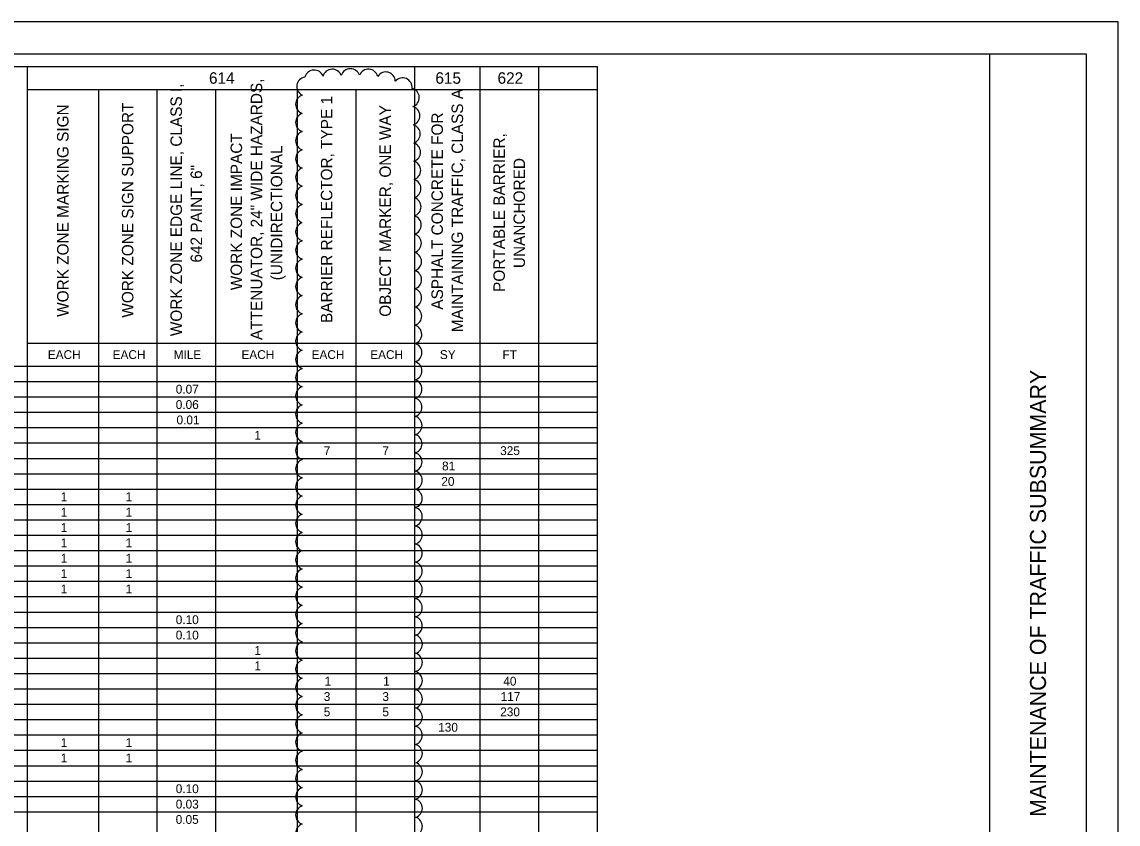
# Model space of a CAD drawing. Extents: x 0 to 36.6, y 0 to 22.
# Drawn here: x 16.89 to 34, y 9.47 to 22 of the extents above; entities that cross this region are included whole.
import ezdxf

# ---------------------------------------------------------------- set-up
doc = ezdxf.new("R2010")
doc.units = 0
for name, color, linetype in [('SC_Scratch2', 7, 'Continuous'), ('SH_Border', 7, 'Continuous'), ('SH_Cut_Line', 7, 'Continuous'), ('SH_Data', 7, 'Continuous'), ('SH_Text', 7, 'Continuous')]:
    doc.layers.add(name, color=color, linetype=linetype)

msp = doc.modelspace()

# ---------------------------------------------------------------- linework, layer by layer
at = {"layer": 'SC_Scratch2'}
for centre, start, end in [((21.452, 21.1), 19.92, 164.92), ((21.736, 21.112), 19.92, 164.92), ((22.02, 21.12), 18.4457, 163.4457), ((22.301, 21.113), 13.9243, 158.9243), ((22.571, 21.069), 2.3412, 147.3412), ((21.332, 20.991), 99.2884, 244.2884), ((22.833, 20.977), 354.1206, 139.1206), ((22.944, 20.818), 290.3797, 75.3797), ((21.312, 20.714), 107.5, 252.5), ((21.312, 20.43), 107.5, 252.5), ((22.954, 20.534), 288.8404, 73.8404), ((22.96, 20.25), 288.4592, 73.4592), ((21.312, 20.145), 107.5, 252.5), ((22.964, 19.966), 288.2577, 73.2577), ((21.312, 19.86), 107.5, 252.5), ((21.312, 19.576), 107.5, 252.5), ((22.967, 19.681), 288.1278, 73.1278), ((22.97, 19.397), 288.035, 73.035), ((21.312, 19.291), 107.5, 252.5), ((22.973, 19.112), 287.9644, 72.9644), ((21.312, 19.007), 107.5, 252.5), ((21.312, 18.722), 107.5, 252.5), ((22.975, 18.828), 287.9084, 72.9084), ((22.977, 18.543), 287.8626, 72.8626), ((21.312, 18.437), 107.5, 252.5), ((22.979, 18.258), 287.8242, 72.8242), ((21.312, 18.153), 107.5, 252.5), ((21.312, 17.868), 107.5, 252.5), ((22.98, 17.974), 287.7913, 72.7913), ((22.982, 17.689), 287.7629, 72.7629), ((21.312, 17.584), 107.5, 252.5), ((22.983, 17.405), 287.7379, 72.7379), ((21.312, 17.299), 107.5, 252.5), ((21.312, 17.014), 107.5, 252.5), ((22.984, 17.12), 287.7157, 72.7157), ((22.985, 16.835), 287.6959, 72.6959), ((21.312, 16.73), 107.5, 252.5), ((22.986, 16.551), 287.678, 72.678), ((21.312, 16.445), 107.5, 252.5), ((21.312, 16.16), 107.5, 252.5), ((22.987, 16.266), 287.6617, 72.6617), ((22.987, 15.982), 287.6469, 72.6469), ((21.312, 15.876), 107.5, 252.5), ((22.988, 15.697), 287.6332, 72.6332), ((21.312, 15.591), 107.5, 252.5), ((21.312, 15.307), 107.5, 252.5), ((22.989, 15.412), 287.6207, 72.6207), ((22.989, 15.128), 287.609, 72.609), ((21.312, 15.022), 107.5, 252.5), ((22.99, 14.843), 287.5982, 72.5982), ((21.312, 14.737), 107.5, 252.5), ((21.312, 14.453), 107.5, 252.5), ((22.99, 14.559), 287.5881, 72.5881), ((22.991, 14.274), 287.5787, 72.5787), ((21.312, 14.168), 107.5, 252.5), ((22.991, 13.989), 287.5698, 72.5698), ((21.312, 13.883), 107.5, 252.5), ((21.312, 13.599), 107.5, 252.5), ((22.991, 13.705), 287.5615, 72.5615), ((22.992, 13.42), 287.5536, 72.5536), ((21.312, 13.314), 107.5, 252.5), ((22.992, 13.136), 287.5462, 72.5462), ((21.312, 13.03), 107.5, 252.5), ((21.312, 12.745), 107.5, 252.5), ((22.992, 12.851), 287.5392, 72.5392), ((22.992, 12.566), 287.5325, 72.5325), ((21.312, 12.46), 107.5, 252.5), ((21.312, 12.176), 107.5, 252.5), ((22.993, 12.282), 287.5262, 72.5262), ((21.312, 11.891), 107.5, 252.5), ((22.993, 11.997), 287.5201, 72.5201), ((22.993, 11.712), 287.5144, 72.5144), ((21.312, 11.607), 107.5, 252.5), ((21.312, 11.322), 107.5, 252.5), ((22.993, 11.428), 287.5089, 72.5089), ((21.312, 11.037), 107.5, 252.5), ((22.993, 11.143), 287.5036, 72.5036), ((22.993, 10.859), 287.5001, 72.5001), ((21.312, 10.753), 107.5017, 252.5017), ((21.312, 10.468), 107.5051, 252.5051), ((22.993, 10.574), 287.5, 72.5), ((21.312, 10.183), 107.5087, 252.5087), ((22.993, 10.289), 287.5, 72.5), ((22.993, 10.005), 287.5, 72.5), ((21.312, 9.899), 107.5125, 252.5125), ((21.312, 9.614), 107.5164, 252.5164), ((22.993, 9.72), 287.5, 72.5), ((21.312, 9.33), 107.5205, 252.5205), ((22.993, 9.436), 287.5, 72.5)]:
    msp.add_arc(centre, 0.149, start, end, dxfattribs=at)
at = {"layer": 'SH_Border'}
msp.add_line((32, 0.5), (32, 21.5), dxfattribs=at)
msp.add_lwpolyline([(1.5, 21.5), (33.5, 21.5), (33.5, 0.5), (1.5, 0.5)], close=True, dxfattribs=at)
at = {"layer": 'SH_Cut_Line'}
msp.add_lwpolyline([(0, 0), (34, 0), (34, 22), (0, 22)], close=True, dxfattribs=at)
at = {"layer": 'SH_Text'}
for p, q in [((9.145, 21.304), (25.87, 21.304)), ((16.975, 21.304), (16.975, 0.679)), ((23.02, 21.304), (23.02, 0.679)), ((24.04, 21.304), (24.04, 0.679)), ((24.955, 21.304), (24.955, 0.679)), ((25.87, 21.304), (25.87, 0.679)), ((16.975, 20.944), (25.87, 20.944)), ((18.085, 20.944), (18.085, 0.679)), ((19, 20.944), (19, 0.679)), ((19.915, 20.944), (19.915, 0.679)), ((21.19, 20.944), (21.19, 0.679)), ((22.105, 20.944), (22.105, 0.679)), ((16.975, 16.984), (25.87, 16.984)), ((9.145, 16.624), (25.87, 16.624)), ((9.145, 16.384), (25.87, 16.384)), ((9.145, 16.144), (25.87, 16.144)), ((9.145, 15.904), (25.87, 15.904)), ((9.145, 15.664), (25.87, 15.664)), ((9.145, 15.424), (25.87, 15.424)), ((9.145, 15.184), (25.87, 15.184)), ((9.145, 14.944), (25.87, 14.944)), ((9.145, 14.704), (25.87, 14.704)), ((9.145, 14.464), (25.87, 14.464)), ((9.145, 14.224), (25.87, 14.224)), ((9.145, 13.984), (25.87, 13.984)), ((9.145, 13.744), (25.87, 13.744)), ((9.145, 13.504), (25.87, 13.504)), ((9.145, 13.264), (25.87, 13.264)), ((9.145, 13.024), (25.87, 13.024)), ((9.145, 12.784), (25.87, 12.784)), ((9.145, 12.544), (25.87, 12.544)), ((9.145, 12.304), (25.87, 12.304)), ((9.145, 12.064), (25.87, 12.064)), ((9.145, 11.824), (25.87, 11.824)), ((9.145, 11.584), (25.87, 11.584)), ((9.145, 11.344), (25.87, 11.344)), ((9.145, 11.104), (25.87, 11.104)), ((9.145, 10.864), (25.87, 10.864)), ((9.145, 10.624), (25.87, 10.624)), ((9.145, 10.384), (25.87, 10.384)), ((9.145, 10.144), (25.87, 10.144)), ((9.145, 9.904), (25.87, 9.904)), ((9.145, 9.664), (25.87, 9.664))]:
    msp.add_line(p, q, dxfattribs=at)

# ---------------------------------------------------------------- texts
at = {"layer": 'SH_Data'}
msp.add_text('MAINTENANCE OF TRAFFIC SUBSUMMARY', height=0.25, rotation=90, dxfattribs=at).set_placement((32.875, 9.584))
at = {"layer": 'SH_Text'}
for s, height, p in [('614', 0.1794, (19.812, 21.034)), ('615', 0.1794, (23.345, 21.034)), ('622', 0.1794, (24.315, 21.034)), ('EACH', 0.138, (17.296, 16.735)), ('EACH', 0.138, (18.308, 16.735)), ('MILE', 0.138, (19.26, 16.735)), ('EACH', 0.138, (20.318, 16.735)), ('EACH', 0.138, (21.413, 16.735)), ('EACH', 0.138, (22.328, 16.735)), ('SY', 0.138, (23.415, 16.735)), ('FT', 0.138, (24.393, 16.735)), ('0.07', 0.138, (19.293, 16.195)), ('0.06', 0.138, (19.293, 15.955)), ('0.01', 0.138, (19.305, 15.715)), ('1', 0.138, (20.52, 15.475)), ('7', 0.138, (21.603, 15.235)), ('7', 0.138, (22.518, 15.235)), ('325', 0.138, (24.356, 15.235)), ('81', 0.138, (23.449, 14.995)), ('20', 0.138, (23.438, 14.755)), ('1', 0.138, (17.498, 14.515)), ('1', 0.138, (18.51, 14.515)), ('1', 0.138, (17.498, 14.275)), ('1', 0.138, (18.51, 14.275)), ('1', 0.138, (17.498, 14.035)), ('1', 0.138, (18.51, 14.035)), ('1', 0.138, (17.498, 13.795)), ('1', 0.138, (18.51, 13.795)), ('1', 0.138, (17.498, 13.555)), ('1', 0.138, (18.51, 13.555)), ('1', 0.138, (17.498, 13.315)), ('1', 0.138, (18.51, 13.315)), ('1', 0.138, (17.498, 13.075)), ('1', 0.138, (18.51, 13.075)), ('0.10', 0.138, (19.293, 12.595)), ('0.10', 0.138, (19.293, 12.355)), ('1', 0.138, (20.52, 12.115)), ('1', 0.138, (20.52, 11.875)), ('1', 0.138, (21.615, 11.635)), ('1', 0.138, (22.53, 11.635)), ('40', 0.138, (24.405, 11.635)), ('3', 0.138, (21.603, 11.395)), ('3', 0.138, (22.518, 11.395)), ('117', 0.138, (24.363, 11.395)), ('5', 0.138, (21.603, 11.155)), ('5', 0.138, (22.518, 11.155)), ('230', 0.138, (24.357, 11.155)), ('130', 0.138, (23.389, 10.915)), ('1', 0.138, (17.498, 10.675)), ('1', 0.138, (18.51, 10.675)), ('1', 0.138, (17.498, 10.435)), ('1', 0.138, (18.51, 10.435)), ('0.10', 0.138, (19.293, 9.955)), ('0.03', 0.138, (19.293, 9.715)), ('0.05', 0.138, (19.292, 9.475))]:
    msp.add_text(s, height=height, dxfattribs=at).set_placement(p)
for s, p in [('ATTENUATOR, 24" WIDE HAZARDS, ', (20.642, 17.032)), ('WORK ZONE EDGE LINE, CLASS I, ', (19.39, 17.092)), ('MAINTAINING TRAFFIC, CLASS A', (23.777, 17.154)), ('WORK ZONE SIGN SUPPORT', (18.632, 17.381)), ('BARRIER REFLECTOR, TYPE 1', (21.737, 17.298)), ('WORK ZONE MARKING SIGN', (17.62, 17.394)), ('OBJECT MARKER, ONE WAY', (22.652, 17.395)), ('ASPHALT CONCRETE FOR ', (23.463, 17.506)), ('WORK ZONE IMPACT ', (20.328, 17.809)), ('PORTABLE BARRIER, ', (24.43, 17.783)), ('(UNIDIRECTIONAL', (20.956, 17.965)), ('UNANCHORED', (24.744, 18.155)), ('642 PAINT, 6"', (19.704, 18.241))]:
    msp.add_text(s, height=0.1794, rotation=90, dxfattribs=at).set_placement(p)

doc.saveas('drawing.dxf')
